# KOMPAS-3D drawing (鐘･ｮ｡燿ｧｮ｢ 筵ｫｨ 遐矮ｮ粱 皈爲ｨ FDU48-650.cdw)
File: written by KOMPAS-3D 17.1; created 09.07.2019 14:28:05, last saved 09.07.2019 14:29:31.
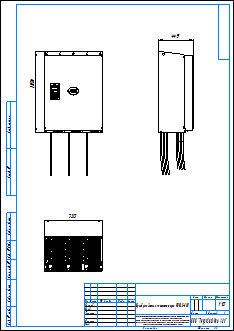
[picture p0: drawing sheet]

Sheet 1: A3, portrait

Title block, sheet 1: name: Преобразователи частоты серии FDU48-650; sheets: 1; sheet format: A3; stored path: \\adlc.lan\data\АДЛ_ПКД\3D-модели\Поставщики\Оборудование Emotron\Преобразователи частоты\Серия FDU 2.0\KOMPAS 2D\Преобразователи частоты серии FDU48-650.cdw

Views: Вид 1
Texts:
  user
  CONTINUOUS_RGB_0_0_0_THICK_0.18
  POLYLINE_STYLE_0.18_RGB_0_0_0
  Рама для чертежей
  Лит-Масса-Масштаб
  Материал-Предприятие
  Масштаб
  Изм.
  Лист
  № докум.
  Подп.
  Дата
  Лит.
  Разраб.
  Пров.
  Т.контр.
  Листов
  Внимание! Данный продукт является объектом авторского права ООО «Торговый Дом АДЛ».
  Запрещается изменение, копирование, распространение
  (в том числе путем копирования на другие сайты и ресурсы в Интернете)
  или любое иное использование информации и объектов без предварительного
  согласия правообладателя (ООО «Торговый Дом АДЛ»).
  Н.контр.
  Утв.
  ООО "Торговый дом АДЛ"
  Изменение
  Номер документа
  Подпись
  Обозначение документа
  Наименование изделия
  Масса изделия по ГОСТ 2.109-73
  Порядковый номер листа
  Общее количество листов в документе
  Характер работы, выполненной лицом, подписавшим документ
  Наименование или индекс предприятия, выпускающего документ
  Инв. № подл.
  Подп. и дата
  Взам. инв. №
  Инв. № дубл.
  Инвентарный номер подлинника по ГОСТ 2.501-68
  Подпись принявшего подлинник в отдел технической документации
  Инвентарный номер подлинника, взамен которого выпущен данный подлинник
  Инвентарный номер дубликата по ГОСТ 2.502-68
  Подпись принявшего дубликат в отдел технической документации
  Справ. №
  Перв. примен.
  Обозначение документа, взамен или на основании которого выпущен данный документ
  Обозначение документа, в котором впервые записан данный документ
  Подпись лица, копировавшего чертеж
  Обозначение формата листа
  !Рама для чертежа
Dimensions and other numbers on the sheet: 1036; 449; 730; 1:10; 1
